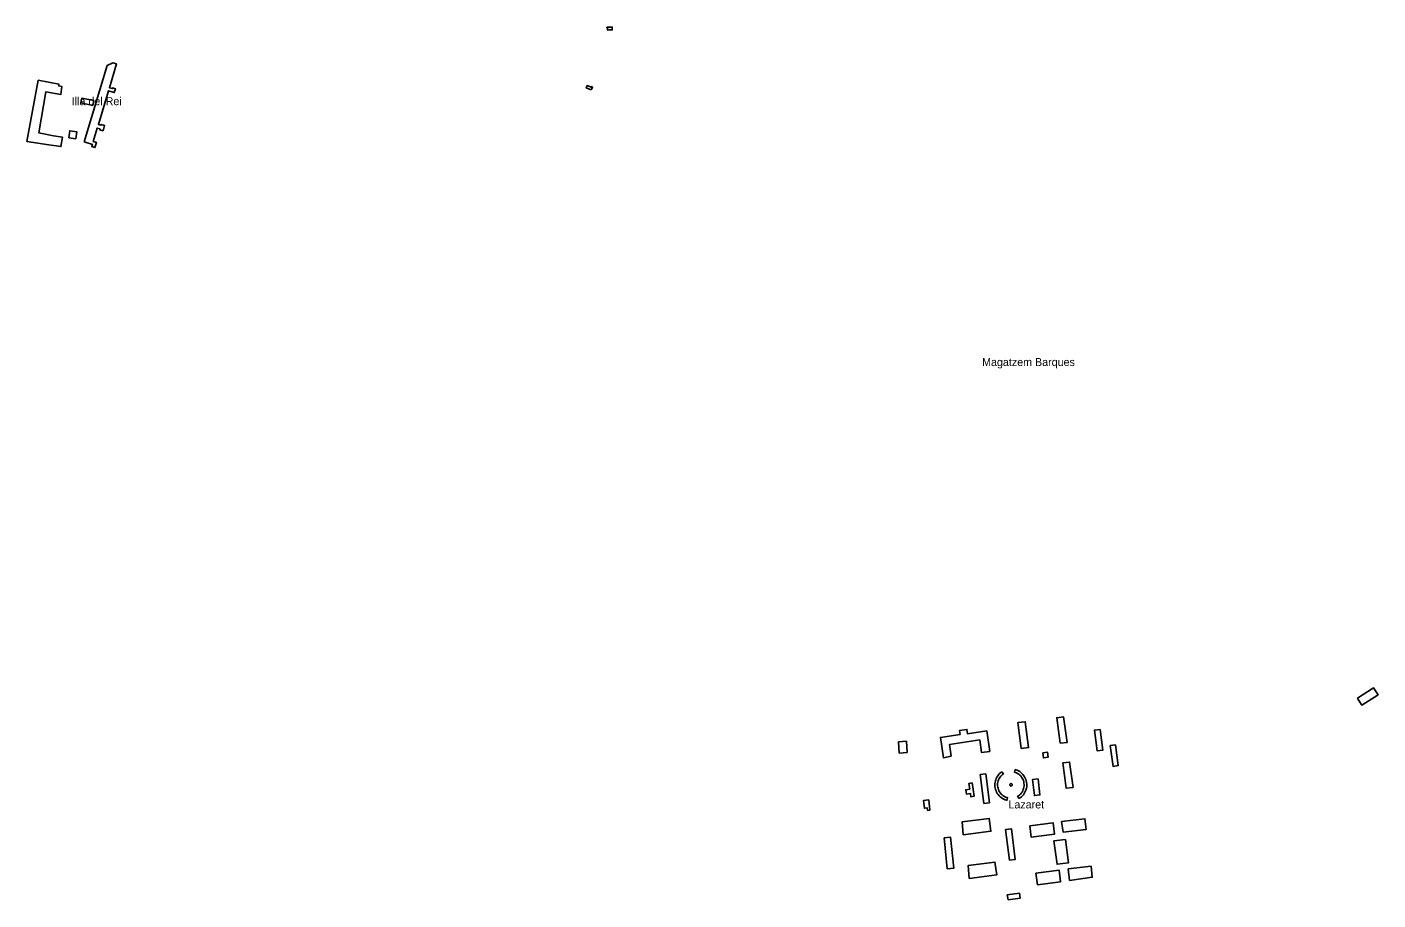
# Model space of a CAD drawing. Extents: x 599451 to 612034, y 4411179 to 4428219.
# Drawn here: x 610008 to 612034, y 4414769 to 4416078 of the extents above; entities that cross this region are included whole.
import ezdxf

# ---------------------------------------------------------------- set-up
doc = ezdxf.new("R2010")
doc.units = 0
doc.layers.add('Bé Arquitectònic', color=7, linetype='Continuous')

msp = doc.modelspace()

# ---------------------------------------------------------------- linework, layer by layer
at = {"layer": 'Bé Arquitectònic'}
for points in [[(610881.1, 4416073.3), (610885.6, 4416073.4), (610885.4, 4416077.7), (610883.5, 4416077.6), (610878.1, 4416077.4), (610877.4, 4416077.4), (610877.5, 4416076.4), (610878.3, 4416076.5), (610878.4, 4416073.2)], [(610093.6, 4415905.5), (610105.9, 4415901.8), (610104.9, 4415898.4), (610109.6, 4415897), (610111.9, 4415904.7), (610107, 4415906.1), (610113, 4415926.3), (610117.2, 4415925), (610116.8, 4415923.7), (610121.7, 4415922.3), (610124, 4415930.1), (610118.9, 4415931.6), (610118.6, 4415930.6), (610114.8, 4415931.7), (610129.8, 4415982.1), (610138.6, 4415979.4), (610140.3, 4415985.1), (610135.9, 4415986.4), (610135.6, 4415985.5), (610131.3, 4415986.7), (610141.8, 4416022.3), (610136.2, 4416024), (610128.1, 4416020)], [(610024.5, 4415997.9), (610007.7, 4415906.1), (610040.3, 4415901.3), (610058.5, 4415898.4), (610061, 4415912.4), (610047.6, 4415914.4), (610025.3, 4415919.2), (610035.8, 4415980.5), (610058.5, 4415976.6), (610060.1, 4415988.4), (610055.3, 4415989.4), (610055.6, 4415991.9)], [(610856, 4415987.3), (610856.1, 4415987.5), (610854.3, 4415988.3), (610853.8, 4415987.3), (610847.9, 4415989.9), (610846.5, 4415986.7), (610852.6, 4415984.2), (610853.6, 4415983.8), (610853.7, 4415983.8), (610854.2, 4415984), (610854.7, 4415984.7), (610854.8, 4415985)], [(610107.7, 4415967.5), (610090, 4415971.1), (610088.5, 4415963.8), (610106.2, 4415960.2)], [(610070.2, 4415911.6), (610080.8, 4415910.1), (610082.3, 4415920.7), (610071.7, 4415922.2)], [(612003.4, 4415071.3), (612005.3, 4415068.2), (612009.7, 4415061.2), (612034, 4415076.7), (612027.3, 4415086.8), (612003.3, 4415071.6)], [(611557.4, 4415003.8), (611567.8, 4415005.2), (611562.5, 4415043.5), (611552.1, 4415042.1)], [(611451.8, 4414991.7), (611447.2, 4415022.3), (611418.5, 4415018), (611417.5, 4415024.7), (611406.4, 4415023), (611407.3, 4415017.1), (611377.7, 4415012.7), (611382.3, 4414982.1), (611393.8, 4414984.6), (611391.2, 4415002), (611436.6, 4415008.9), (611439.5, 4414989.8)], [(611498.8, 4414996), (611509.8, 4414997.4), (611504.8, 4415036.2), (611493.9, 4415034.8)], [(611617.1, 4415024.5), (611608.7, 4415023.7), (611612.9, 4414992.4), (611621.2, 4414993.5)], [(611327.6, 4414989.8), (611326.6, 4415006.9), (611314.9, 4415006.2), (611315.9, 4414989.1)], [(611531.3, 4414989.7), (611532.2, 4414982), (611539.1, 4414982.9), (611538.2, 4414990.6)], [(611640.2, 4415001.4), (611632.4, 4415000.3), (611636.7, 4414969.3), (611644.5, 4414970.4)], [(611495.6, 4414920.9), (611497.5, 4414922.2), (611499.2, 4414923.5), (611500.7, 4414925), (611502.2, 4414926.7), (611503.4, 4414928.5), (611504.5, 4414930.4), (611505.5, 4414932.4), (611506.2, 4414934.4), (611506.4, 4414935.2), (611506.7, 4414936.5), (611507.1, 4414938.7), (611507.2, 4414940.9), (611507.2, 4414943.1), (611507, 4414945.2), (611506.5, 4414947.4), (611505.9, 4414949.5), (611505, 4414951.5), (611504, 4414953.4), (611502.8, 4414955.3), (611501.5, 4414957), (611500, 4414958.6), (611498.4, 4414960), (611496.6, 4414961.4), (611494.7, 4414962.5), (611492.8, 4414963.4), (611490.7, 4414964.2), (611489.9, 4414964.4), (611488.9, 4414960.6), (611489.9, 4414960.3), (611491.7, 4414959.6), (611493.5, 4414958.6), (611495.1, 4414957.5), (611496.7, 4414956.3), (611498.1, 4414954.9), (611499.3, 4414953.3), (611500.5, 4414951.6), (611501.4, 4414949.9), (611502.1, 4414948), (611502.7, 4414946.1), (611503, 4414944.2), (611503.2, 4414942.2), (611503.2, 4414941.5), (611503.2, 4414940.2), (611502.9, 4414938.2), (611502.5, 4414936.2), (611501.9, 4414934.4), (611501.1, 4414932.5), (611500.1, 4414930.8), (611498.9, 4414929.2), (611497.6, 4414927.7), (611496.1, 4414926.3), (611494.5, 4414925.1), (611493.3, 4414924.3)], [(611561.1, 4414974.3), (611566.3, 4414936.4), (611576.6, 4414937.8), (611571.4, 4414975.7)], [(611425.3, 4414944.4), (611420.5, 4414943.7), (611421.8, 4414934.9), (611415.8, 4414934.1), (611416.7, 4414927.8), (611422.6, 4414928.6), (611423.3, 4414923.8), (611428.1, 4414924.5)], [(611437.2, 4414956.9), (611442.8, 4414913.6), (611451.2, 4414914.7), (611445.6, 4414958)], [(611469.8, 4414961.2), (611468.1, 4414959.9), (611466.4, 4414958.4), (611465, 4414956.8), (611463.6, 4414955), (611462.5, 4414953.2), (611461.5, 4414951.2), (611460.7, 4414949.2), (611460.2, 4414947.8), (611459.8, 4414945.6), (611459.5, 4414943.5), (611459.4, 4414941.3), (611459.5, 4414939.1), (611459.8, 4414936.9), (611460.3, 4414934.8), (611461.1, 4414932.7), (611461.9, 4414930.7), (611463, 4414928.8), (611464.2, 4414927), (611465.7, 4414925.3), (611467.2, 4414923.8), (611468.9, 4414922.4), (611470.7, 4414921.1), (611472.6, 4414920.1), (611474.6, 4414919.2), (611476.7, 4414918.5), (611477.4, 4414918.3), (611478.5, 4414922.3), (611477.4, 4414922.6), (611475.5, 4414923.3), (611473.7, 4414924.1), (611472, 4414925.2), (611470.4, 4414926.4), (611469, 4414927.8), (611467.7, 4414929.3), (611466.5, 4414930.9), (611465.5, 4414932.6), (611464.7, 4414934.5), (611464.1, 4414936.4), (611463.7, 4414938.3), (611463.5, 4414940.3), (611463.4, 4414941.5), (611463.5, 4414943.5), (611463.8, 4414945.5), (611464.3, 4414947.4), (611465, 4414949.3), (611465.9, 4414951.1), (611466.9, 4414952.8), (611468.2, 4414954.4), (611469.5, 4414955.8), (611471, 4414957.2), (611472.2, 4414958)], [(611481.9, 4414942.2), (611481.8, 4414941.8), (611481.8, 4414941.2), (611482.1, 4414940.7), (611482.5, 4414940.2), (611483, 4414939.9), (611483.6, 4414939.8), (611484.2, 4414939.9), (611484.7, 4414940.2), (611485.1, 4414940.7), (611485.3, 4414941), (611485.3, 4414941.2), (611485.4, 4414941.8), (611485.2, 4414942.4), (611484.9, 4414942.9), (611484.4, 4414943.2), (611483.8, 4414943.4), (611483.2, 4414943.4), (611482.7, 4414943.2), (611482.2, 4414942.8)], [(611524.1, 4414950.5), (611516, 4414949.6), (611518.7, 4414925.5), (611526.9, 4414926.4)], [(611361.9, 4414903.7), (611360.2, 4414918.9), (611352.3, 4414918), (611353.7, 4414906.5), (611357.9, 4414907), (611358.4, 4414903.2)], [(611411.7, 4414866.6), (611453.3, 4414871.9), (611450.8, 4414891.1), (611410.3, 4414885.9)], [(611511.6, 4414880.3), (611513.9, 4414863.1), (611548.7, 4414867.5), (611546.6, 4414884.7)], [(611559.5, 4414886.5), (611562, 4414870.5), (611596.3, 4414874.8), (611594.3, 4414890.8)], [(611383.1, 4414862.1), (611388, 4414815.6), (611397.8, 4414816.6), (611392.9, 4414863.1)], [(611475.2, 4414874.6), (611481.1, 4414828.7), (611489.9, 4414829.8), (611484.1, 4414875.7)], [(611548, 4414857.5), (611552.6, 4414822.4), (611569.7, 4414824.6), (611565.1, 4414859.6)], [(611420.9, 4414801.2), (611462.1, 4414806.6), (611459.5, 4414825.8), (611419.1, 4414820.4)], [(611523.4, 4414791.4), (611558, 4414796.3), (611555.6, 4414813.7), (611520.8, 4414808.9)], [(611571.5, 4414798.2), (611605.5, 4414802.9), (611603.6, 4414819.5), (611569.3, 4414815.5)], [(611479.1, 4414769), (611497.2, 4414771.6), (611496.1, 4414779.2), (611478, 4414776.6)]]:
    msp.add_lwpolyline(points, close=True, dxfattribs=at)

# ---------------------------------------------------------------- texts
for s, p in [('Illa del Rei', (610074.8, 4415960.5)), ('Magatzem Barques', (611440.2, 4415569.4)), ('Lazaret', (611479.7, 4414906.2))]:
    msp.add_text(s, height=12, dxfattribs=at).set_placement(p)

doc.saveas('drawing.dxf')
